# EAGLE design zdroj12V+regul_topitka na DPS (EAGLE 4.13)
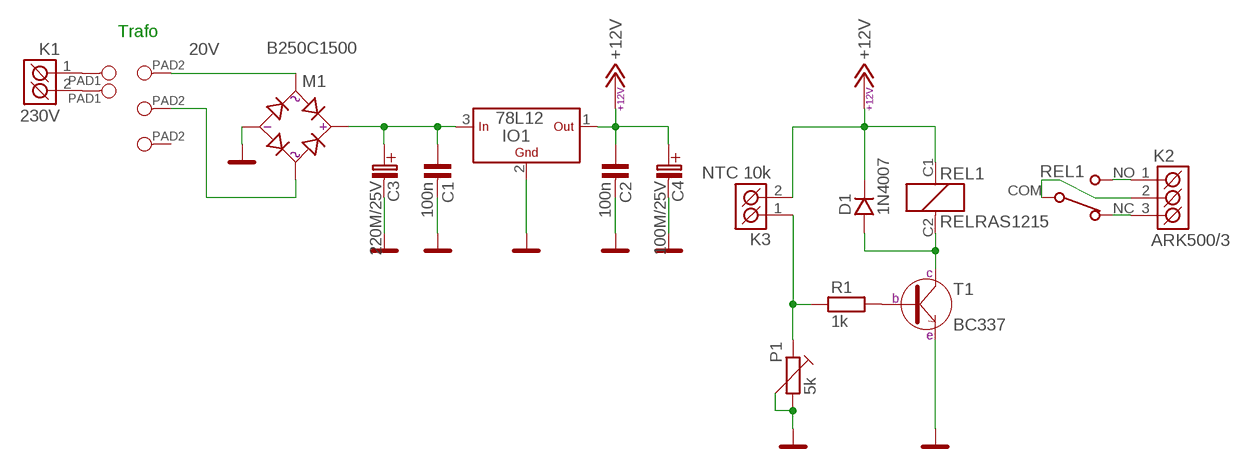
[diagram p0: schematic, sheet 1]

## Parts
C1  100n  C-KERAMIK_5  [C-5]
C2  100n  C-KERAMIK_5  [C-5]
C3  220M/25V  [C_EL_3,5]
C4  100M/25V  [C_EL_2,5]
D1  1N4007  1N4007_SMD_SM-1  [SM-1]
IO1  78L12  78L_TO-92_TO-92  [TO-92]
K1  230V  ARK500/2  [ARK500/2]
K2  ARK500/3  [ARK500/3]
K3  NTC 10k  ARK500/2  [ARK500/2]
M1  B250C1500  D-MUSTEK_B250C1500  [DM_WOM]
P1  5k  TRIMRPT10V  [PT10V]
PAD1  PAD_2  [PAD_2]
PAD2  PAD_3  [PAD_3]
R1  1k  R_7,5  [R-7,5]
REL1  RELRAS1215  RELRAS15  [RELE_RAS]
T1  BC337  [TO-92]

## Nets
20V: M1.AC1 PAD2.1
+12V: C2.1 C4.C+(C_EL+) D1.K IO1.1(OUT) K3.2(K2) REL1.C1(RE:C1)
GND: C1.2 C2.2 C3.C-(C_EL-) C4.C-(C_EL-) IO1.2(GND) M1.- P1.2 P1.3 T1.3(E)
N$1: K1.2(K2) PAD1.2
N$2: K1.1(K1) PAD1.1
N$4: M1.AC2 PAD2.2
N$5: C1.1 C3.C+(C_EL+) IO1.3(IN) M1.+
N$6: K2.1(K1) REL1.NO(SW:NO)
N$7: K2.3(K3) REL1.NC(SW:NC)
N$8: K2.2(K2) REL1.COM(SW:COM)
N$9: R1.2 T1.2(B)
N$10: D1.A REL1.C2(RE:C2) T1.1(C)
N$11: K3.1(K1) P1.1 R1.1
Unconnected: PAD2.3

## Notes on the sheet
- Trafo

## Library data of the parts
C1 C2 = #PaJa_22:C-KERAMIK: Kondenzator - keramicky
C3 = #PaJa_C-el_2:220M/25V
C4 = #PaJa_C-el_2:100M/25V
D1 = #PaJa_22:1N4007: Usmernovaci dioda - 1A, 1000V
IO1 = #PaJa_22:78L??: Stabilizátor - 100mA ?? - napeti => 02, 05, 06, 08, 09, 12, 15, 18
K1 K3 = #PaJa_22:ARK500/2: Svorkovnice - roztec 5mm - dvojita
K2 = #PaJa_22:ARK500/3: Svorkovnice - roztec 5mm - trojita
M1 = #PaJa_22:D-MUSTEK: Diodovy mustek - Graetz
P1 = #PaJa_22:TRIMR: Trimr
PAD1 = #PaJa_22:PAD_2: Pajeci bod - 2,54 mm prumer - 2x
PAD2 = #PaJa_22:PAD_3: Pajeci bod - 2,54 mm prumer - 3x
R1 = #PaJa_22:R: Rezistor
REL1 = #PaJa_22:RELRAS??15: RELE - 1x prepinaci, 5V, 12V, 24V max. spinany proud = 15A
T1 = #PaJa_22:BC337: Tranzistor NPN - Univerzalni NF - Ic=0,5A

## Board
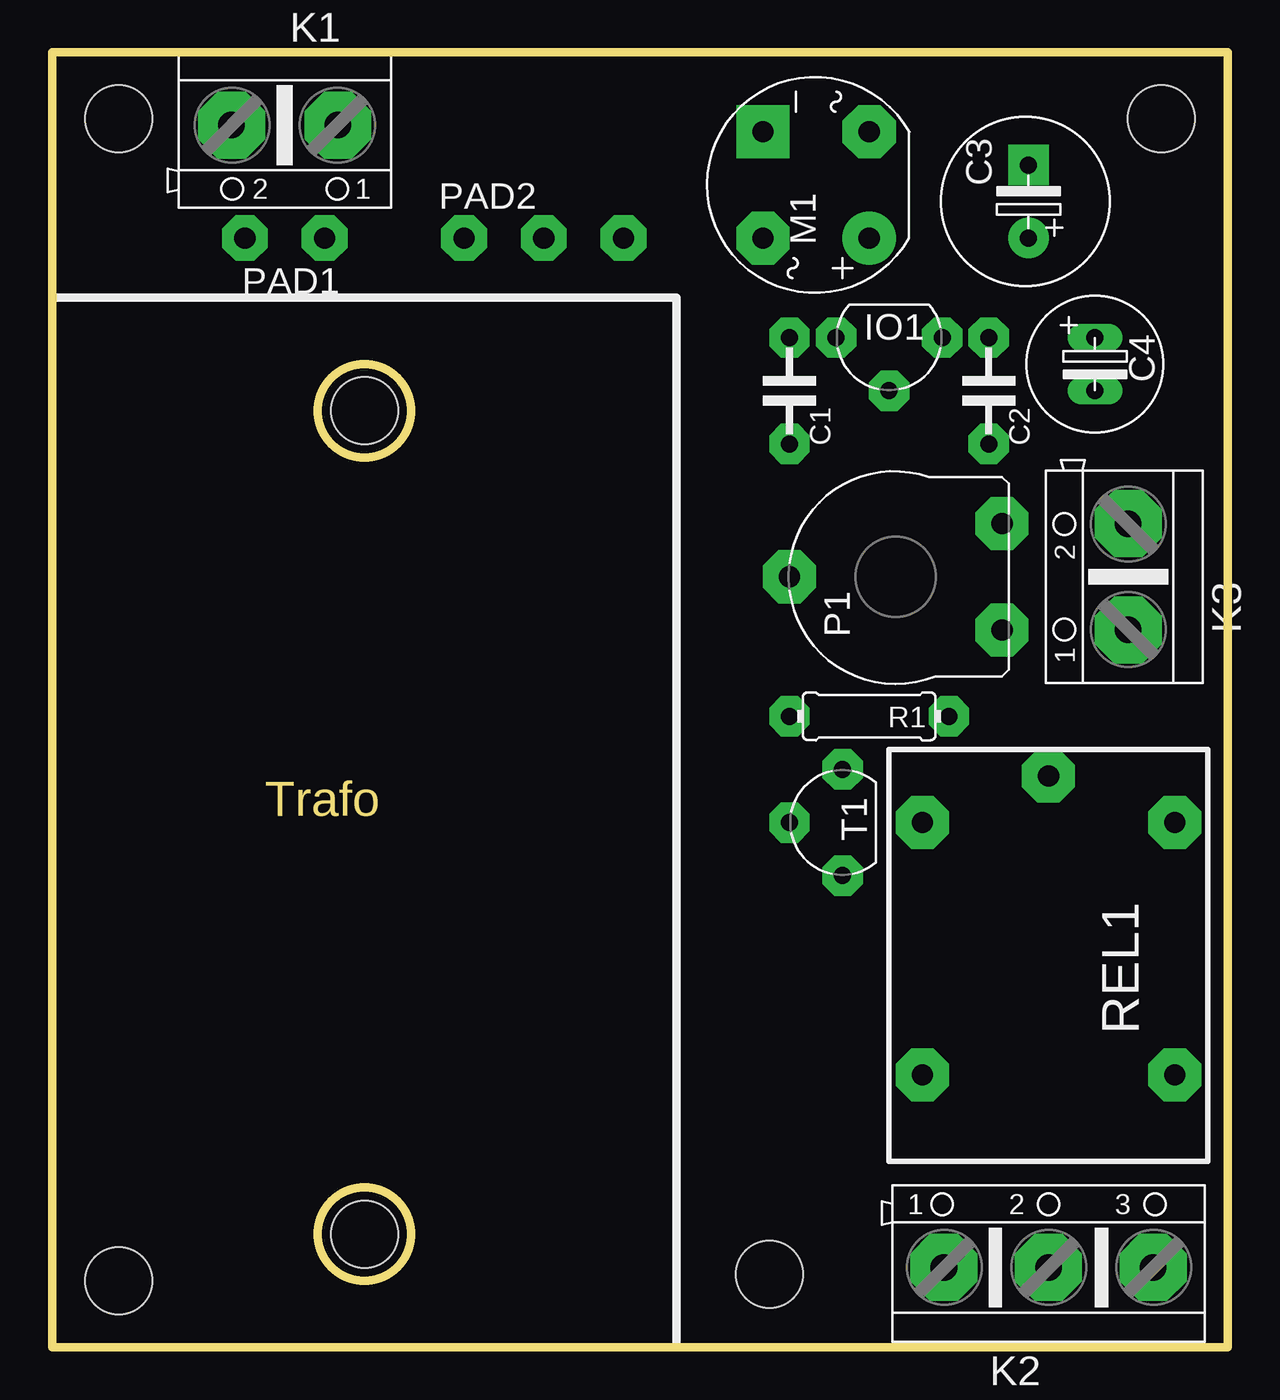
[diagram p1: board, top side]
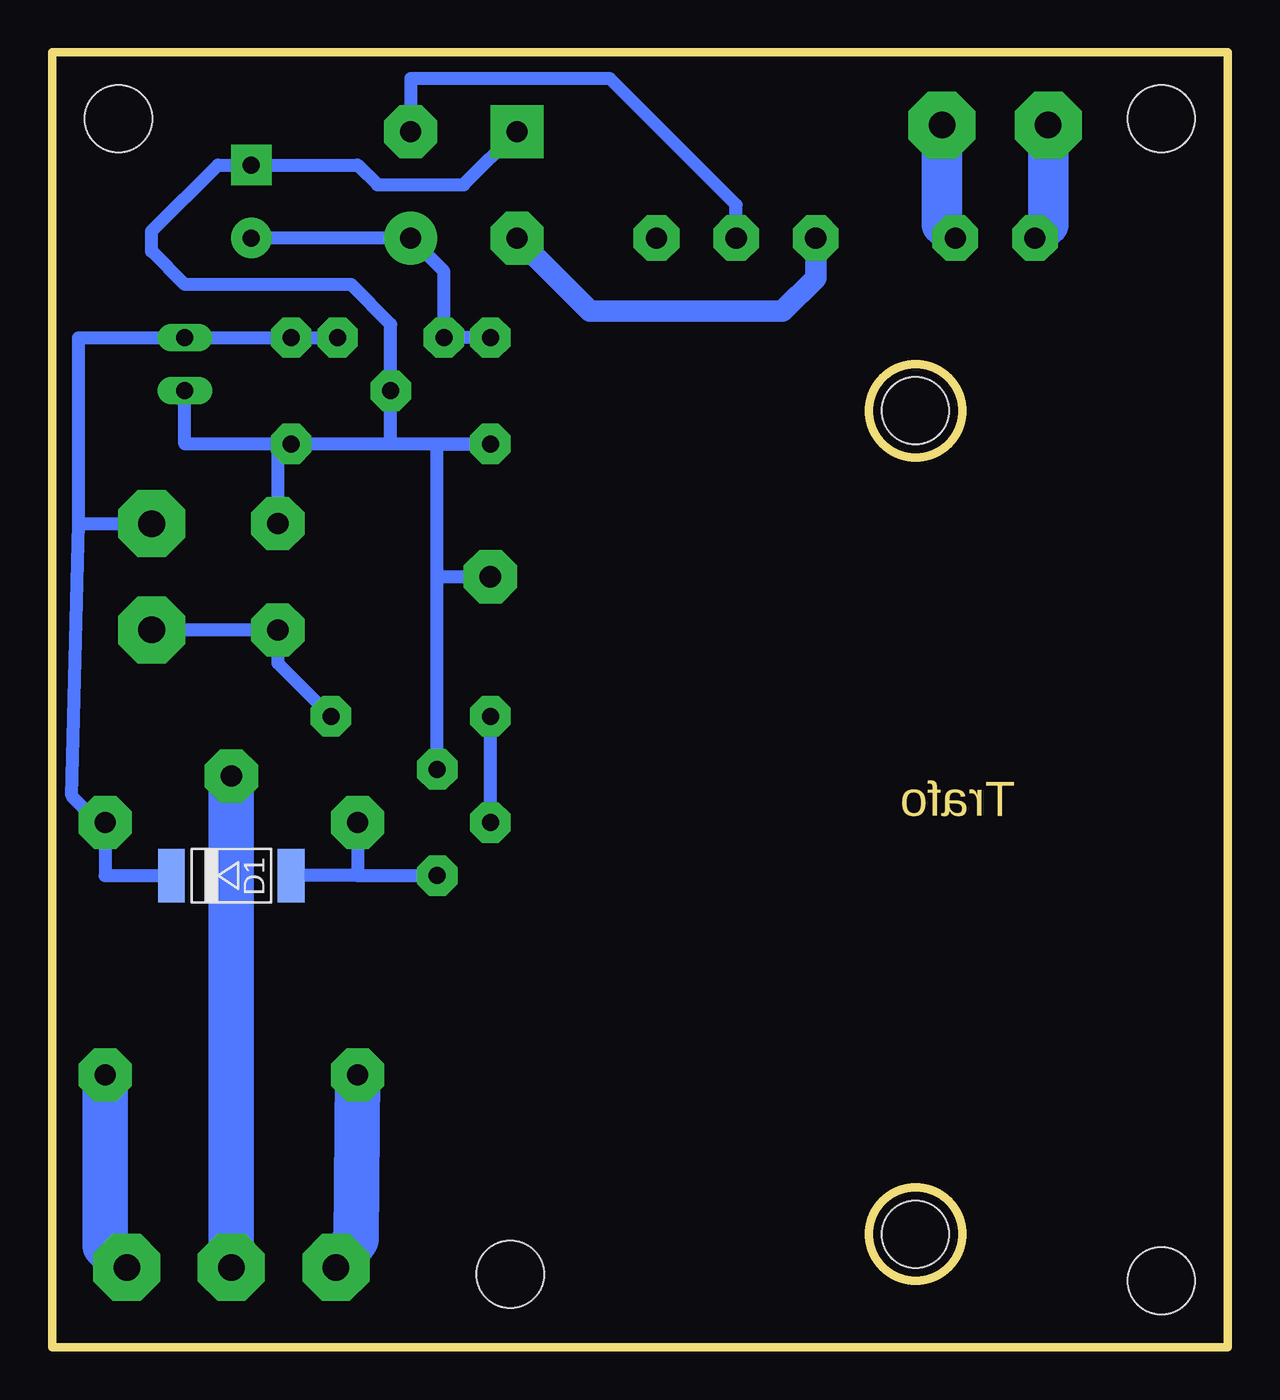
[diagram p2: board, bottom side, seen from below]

Size 56.19 x 61.9 mm. Coordinates in mm from the lower left corner, seen from the top.
Outline: 0,0 56.19,0 56.19,61.9 0,61.9 0,0
Outline: circle at 14.92,5.4 radius 2.22
Outline: circle at 14.92,44.77 radius 2.22
Copper layers (1*16): Top 0.035mm / dielectric 1.5mm / Bottom 0.035mm
Design rules "default": minimum track width 10mil, minimum drill 24mil, track to track 8mil, track to pad 8mil, pad to pad 8mil, via to via 8mil, smd to smd 8mil, copper to edge 40mil, drill to drill 8mil, minimum pad ring 10mil, minimum via ring 8mil, stop-mask expansion 4mil, vias tented up to drill 0mil, thermal gap 10mil
Holes 3.2 mm at 3.17,3.17 3.17,58.74 53.02,58.74 34.29,3.49 14.92,5.4 14.92,44.77

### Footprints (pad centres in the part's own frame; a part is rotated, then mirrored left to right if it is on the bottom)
C-5 = drill 0.813 pad 1.93 octagon: 1 -2.54,0; 2 2.54,0
C_EL_3,5 = drill 0.813 pad 1.93 round: C+ 0,0 | drill 0.813 pad 1.93 square: C- 3.493,0
C_EL_2,5 = drill 0.813 pad 1.27 long: C+ -1.27,0; C- 1.27,0
SM-1 = smd 1.27 x 2.54: A 2.857,0; K -2.857,0
TO-92 = drill 0.813 pad 1.93 octagon: 1 0,2.54; 2 2.54,0; 3 0,-2.54
ARK500/2 = drill 1.27 pad 3.2 octagon: 1 -2.54,0; 2 2.54,0
ARK500/3 = drill 1.27 pad 3.2 octagon: 1 -5,0; 2 0,0; 3 5,0
DM_WOM = drill 1.016 pad 2.54 round: + -2.54,-2.54 | drill 1.016 pad 2.54 square: - 2.54,2.54 | drill 1.016 pad 2.54 octagon: AC1 -2.54,2.54; AC2 2.54,-2.54
PT10V = drill 1.016 pad 2.54 octagon: 1 -2.54,-5.08; 2 2.54,-5.08; 3 0,5.08
PAD_2 = drill 1.016 pad 2.184 octagon: 1 -1.905,0; 2 1.905,0
PAD_3 = drill 1.016 pad 2.184 octagon: 1 -3.81,0; 2 0,0; 3 3.81,0
R-7,5 = drill 0.813 pad 1.93 octagon: 1 -3.81,0; 2 3.81,0
RELE_RAS = drill 1.016 pad 2.54 octagon: C1 -6.35,6.032; C2 -6.35,-6.032; COM -8.572,0; NC 5.715,6.032; NO 5.715,-6.032

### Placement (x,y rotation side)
C1  35.24,45.72 270 top
C2  44.77,45.72 270 top
C3  46.67,53.02 90 top
C4  49.85,46.99 270 top
D1  47.62,22.54 0 bottom
IO1  40.01,48.26 270 top
K1  11.11,58.42 180 top
K2  47.62,3.81 0 top
K3  51.44,36.83 90 top
M1  36.51,55.56 90 top
P1  40.32,36.83 90 top
PAD1  11.11,53.02 180 top
PAD2  23.5,53.02 0 top
R1  39.05,30.16 180 top
REL1  47.62,18.73 270 top
T1  37.78,25.08 180 top

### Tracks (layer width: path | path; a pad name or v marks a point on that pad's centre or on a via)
20V
  Bottom 1.016: PAD2.1 19.68,51.12 21.27,49.53 30.48,49.53 M1.AC1
+12V
  Bottom 0.61: IO1.1 C2.1 C4.C+ 54.93,48.26 54.93,39.37 | 54.93,39.37 K3.2 | 54.93,39.37 55.24,26.35 53.98,25.08 REL1.C1 53.66,22.54 D1.K
GND
  Bottom 0.61: 40.01,43.18 C1.2 37.78,43.18 37.78,36.83 | 40.01,43.18 C2.2 | 40.01,43.18 IO1.2 40.01,48.9 41.91,50.8 49.85,50.8 51.44,52.39 51.44,53.34 48.26,56.52 C3.C- 41.59,56.52 40.64,55.56 36.51,55.56 M1.- | C4.C- 49.85,43.18 C2.2 | T1.3 37.78,36.83 | 37.78,36.83 P1.3 | C2.2 45.4,43.18 P1.2
N$1
  Bottom 1.93: K1.2 8.57,53.66 PAD1.2
N$2
  Bottom 1.93: K1.1 13.65,53.66 PAD1.1
N$4
  Bottom 0.61: M1.AC2 39.05,60.64 29.53,60.64 23.5,54.61 PAD2.2
N$5
  Bottom 0.61: C3.C+ M1.+ 37.47,51.44 IO1.3 C1.1
N$6
  Bottom 2.184: K2.1 41.67,5.16 REL1.NO
N$7
  Bottom 2.184: K2.3 53.66,4.84 REL1.NC
N$8
  Bottom 2.184: K2.2 REL1.COM
N$9
  Bottom 0.61: T1.2 R1.2
N$10
  Bottom 0.61: 41.59,22.54 D1.A | REL1.C2 41.59,22.54 | 41.59,22.54 T1.1
N$11
  Bottom 0.61: K3.1 P1.1 45.4,32.7 R1.1

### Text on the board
Dimension: Trafo
Doplnky: 20V | 230V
